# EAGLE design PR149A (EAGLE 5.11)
PID: 626
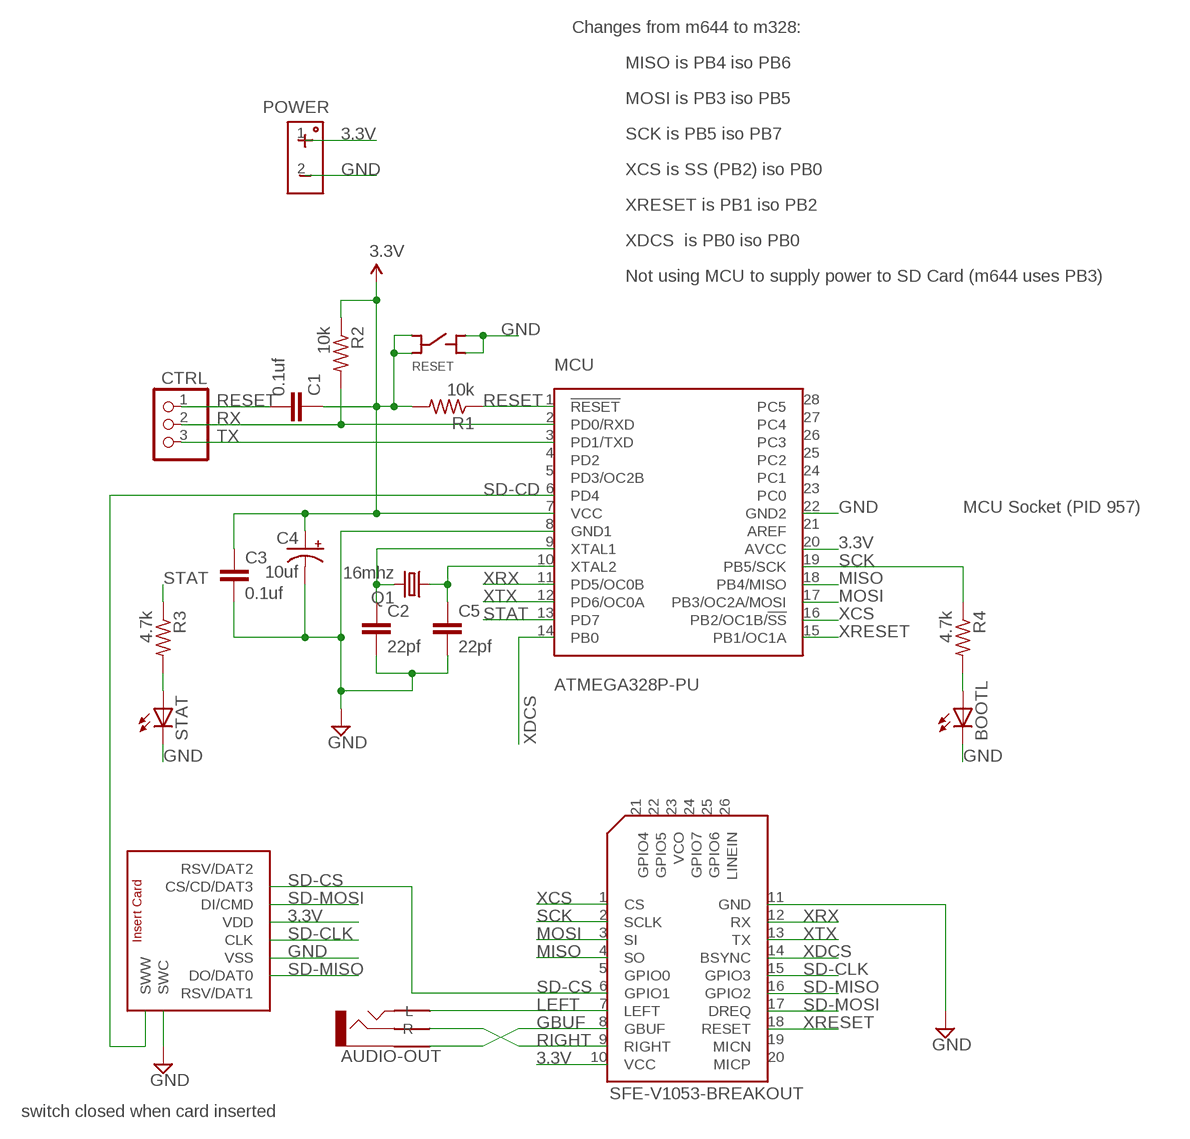
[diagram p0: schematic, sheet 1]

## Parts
AUDIO-OUT  AUDIO-JACK-STEREO-3PIN955  [AUDIO-JACK-STEREO-3PIN-955]
BOOTL  LED5MM  [LED5MM]
C1  0.1uf  C-EUC1206  [C1206]
C2  22pf  C-EUC0805  [C0805]
C3  0.1uf  C-EUC1206  [C1206]
C4  10uf  CPOL-USB  [PANASONIC_B]
C5  22pf  C-EUC0805  [C0805]
CTRL  PINHD-1X3  [1X03]
MCU  ATMEGA328P-PU  [DIL28-3]
POWER  HEADER-POWER  [HEADER-POWER]
Q1  16mhz  CRYSTALHC49S  [HC49/S]
R1  10k  R-US_M0805  [M0805]
R2  10k  R-US_R0805  [R0805]
R3  4.7k  R-US_R1206  [R1206]
R4  4.7k  R-US_R1206  [R1206]
RESET  SFE-PUSHBUTTON-SWITCH  [SFE-PUSHBUTTON-SWITCH]
SFE-V1053-BREAKOUT  SFE-VS1053-BREAKOUT  [SFE-VS1053-BREAKOUT]
STAT  LED5MM  [LED5MM]
U$1  SD-CARD-MICRO947  [SD-CARD-MICRO-947]

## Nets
3.3V: C1.1 C3.1 C4.+ MCU.7(VCC) MCU.20(AVCC) POWER.1 R1.2 R2.1 RESET.C@1(C) RESET.C@2(C) SFE-V1053-BREAKOUT.10(VCC) U$1.VDD
GBUF: AUDIO-OUT.1(COM) SFE-V1053-BREAKOUT.8(GBUF)
GND: BOOTL.K(C) C2.2 C3.2 C4.- C5.2 MCU.8(GND1) MCU.22(GND2) POWER.2 RESET.O@1(O) RESET.O@2(O) SFE-V1053-BREAKOUT.11(GND) STAT.K(C) U$1.SWC U$1.VSS
LEFT: AUDIO-OUT.2(L) SFE-V1053-BREAKOUT.7(LEFT)
MISO: MCU.18(PB4/MISO) SFE-V1053-BREAKOUT.4(SO)
MOSI: MCU.17(PB3/OC2A/MOSI) SFE-V1053-BREAKOUT.3(SI)
N$1: R3.2 STAT.A
N$2: BOOTL.A R4.2
N$3: C2.1 MCU.9(XTAL1) Q1.2
N$6: C5.1 MCU.10(XTAL2) Q1.1
RESET: C1.2 CTRL.1 MCU.1(!RESET) R1.1
RIGHT: AUDIO-OUT.3(R) SFE-V1053-BREAKOUT.9(RIGHT)
RX: CTRL.2 MCU.2(PD0/RXD) R2.2
SCK: MCU.19(PB5/SCK) R4.1 SFE-V1053-BREAKOUT.2(SCLK)
SD-CD: MCU.6(PD4) U$1.SWW
SD-CLK: SFE-V1053-BREAKOUT.15(GPIO3) U$1.CLK
SD-CS: SFE-V1053-BREAKOUT.6(GPIO1) U$1.CD/DAT3(CS/CD/DAT3)
SD-MISO: SFE-V1053-BREAKOUT.16(GPIO2) U$1.DAT0(DO/DAT0)
SD-MOSI: SFE-V1053-BREAKOUT.17(DREQ) U$1.CMD(DI/CMD)
STAT: MCU.13(PD7) R3.1
TX: CTRL.3 MCU.3(PD1/TXD)
XCS: MCU.16(PB2/OC1B/!SS) SFE-V1053-BREAKOUT.1(CS)
XDCS: MCU.14(PB0) SFE-V1053-BREAKOUT.14(BSYNC)
XRESET: MCU.15(PB1/OC1A) SFE-V1053-BREAKOUT.18(RESET)
XRX: MCU.11(PD5/OC0B) SFE-V1053-BREAKOUT.12(RX)
XTX: MCU.12(PD6/OC0A) SFE-V1053-BREAKOUT.13(TX)
Unconnected: MCU.4(PD2) MCU.5(PD3/OC2B) MCU.21(AREF) MCU.23(PC0) MCU.24(PC1) MCU.25(PC2) MCU.26(PC3) MCU.27(PC4) MCU.28(PC5) SFE-V1053-BREAKOUT.5(GPIO0) SFE-V1053-BREAKOUT.19(MICN) SFE-V1053-BREAKOUT.20(MICP) SFE-V1053-BREAKOUT.21(GPIO4) SFE-V1053-BREAKOUT.22(GPIO5) SFE-V1053-BREAKOUT.23(VCO) SFE-V1053-BREAKOUT.24(GPIO7) SFE-V1053-BREAKOUT.25(GPIO6) SFE-V1053-BREAKOUT.26(LINEIN) U$1.DAT1(RSV/DAT1) U$1.DAT2(RSV/DAT2)

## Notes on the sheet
- Changes from m644 to m328:
- MISO is PB4 iso PB6
- MOSI is PB3 iso PB5
- SCK is PB5 iso PB7
- XCS is SS (PB2) iso PB0
- XRESET is PB1 iso PB2
- XDCS  is PB0 iso PB0
- Not using MCU to supply power to SD Card (m644 uses PB3)
- MCU Socket (PID 957)
- switch closed when card inserted

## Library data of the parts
AUDIO-OUT = trl:AUDIO-JACK-STEREO-3PIN
BOOTL STAT = led:LED: LED
C1-C3 C5 = rcl:C-EU: CAPACITOR, European symbol
C4 = rcl:CPOL-US: POLARIZED CAPACITOR, American symbol
CTRL = pinhead:PINHD-1X3: PIN HEADER
MCU = trl:ATMEGA328P-PU
POWER = trl:HEADER-POWER
Q1 = crystal:CRYSTAL: CRYSTAL; OC_FARNELL: 1667008; OC_NEWARK: unknown
R1-R4 = resistor:R-US_: RESISTOR, American symbol
RESET = trl:SFE-PUSHBUTTON-SWITCH
SFE-V1053-BREAKOUT = trl:SFE-VS1053-BREAKOUT
U$1 = trl:SD-CARD-MICRO

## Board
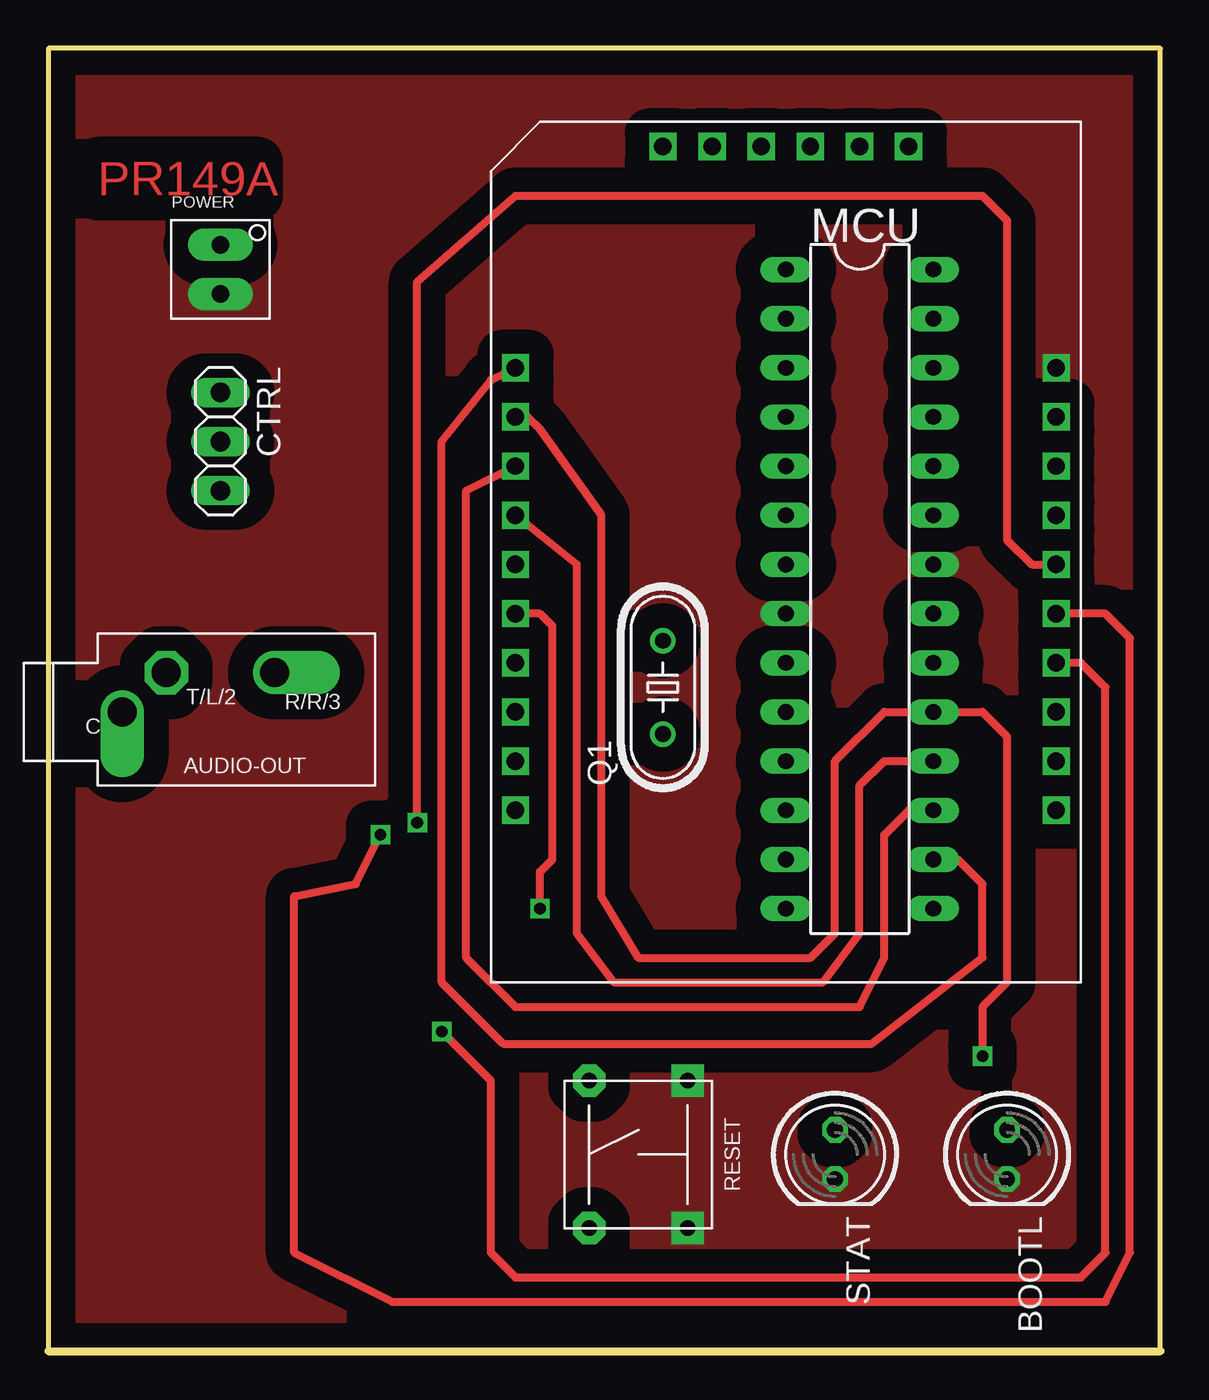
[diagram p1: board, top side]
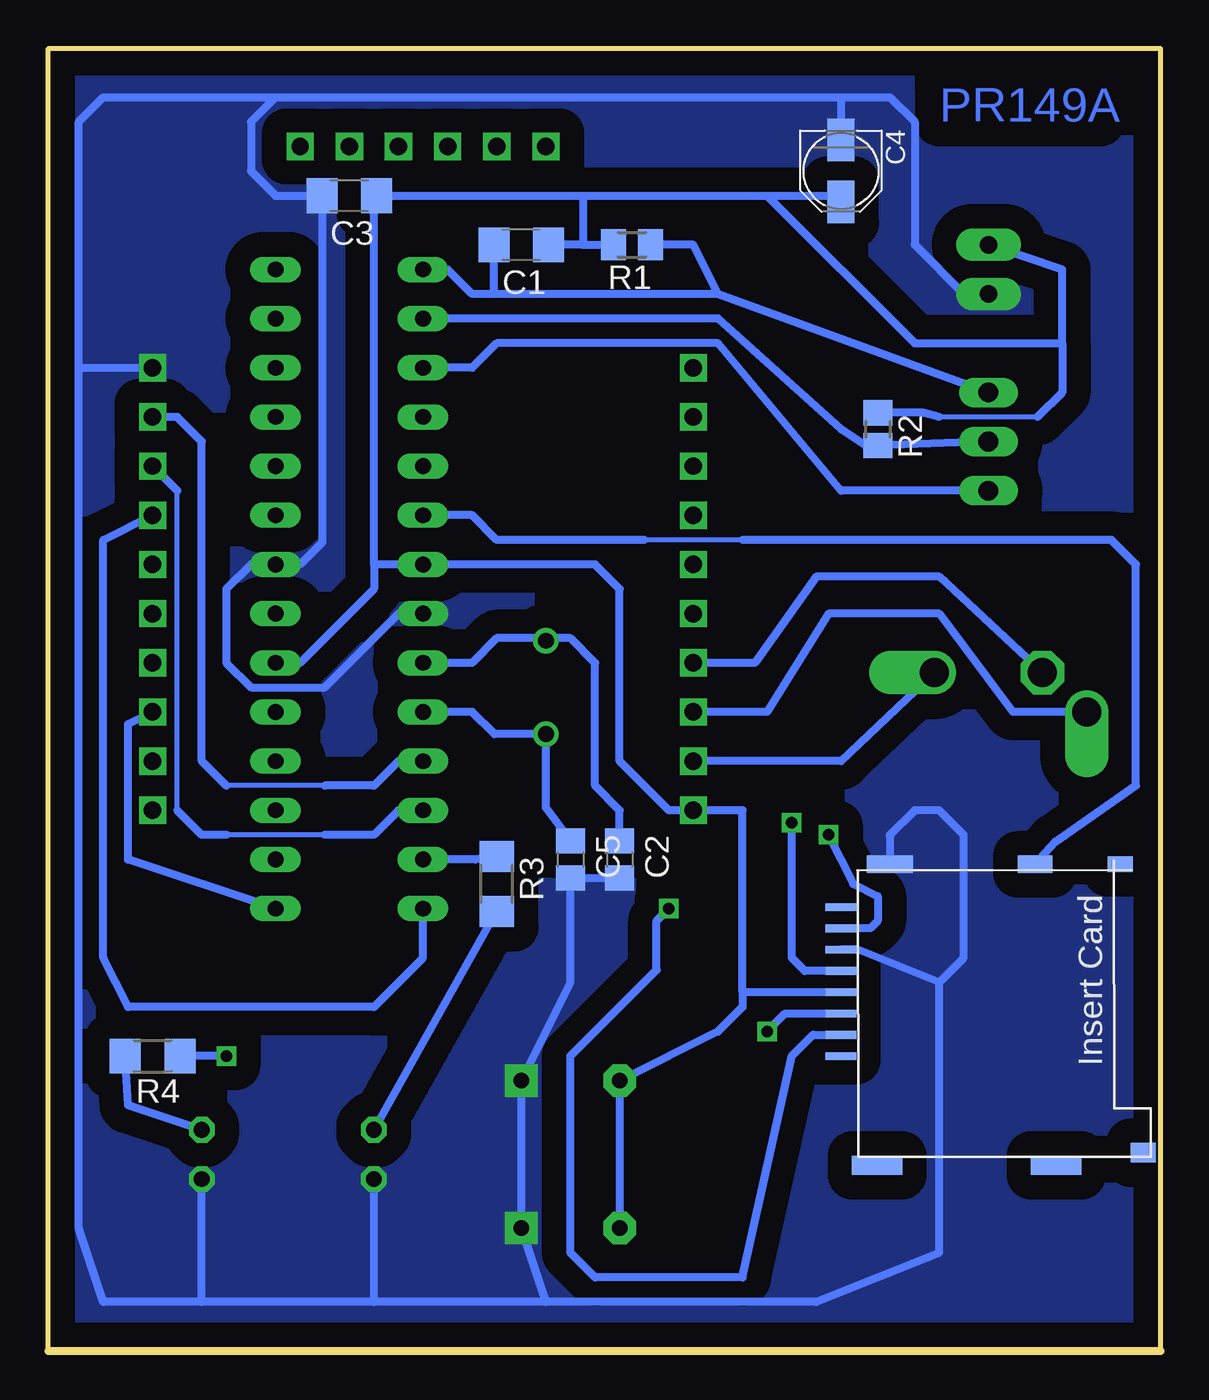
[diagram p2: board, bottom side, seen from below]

Size 57.45 x 67.3 mm. Coordinates in mm from the lower left corner, seen from the top.
Outline: 0,0 57.45,0 57.45,67.3 0,67.3 0,0
Copper layers (1*16): Top 0.035mm / dielectric 1.5mm / Bottom 0.035mm
Design rules "default": minimum track width 10mil, minimum drill 0.6mm, track to track 8mil, track to pad 8mil, pad to pad 8mil, via to via 8mil, smd to smd 8mil, copper to edge 40mil, drill to drill 8mil, minimum pad ring 10mil, minimum via ring 8mil, stop-mask expansion 4mil, vias tented up to drill 0mil, thermal gap 10mil

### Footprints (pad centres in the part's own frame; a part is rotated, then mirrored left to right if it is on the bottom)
AUDIO-JACK-STEREO-3PIN-955 = drill 1.5 offset: 1 0,0; 3 7.874,2.032 | drill 1.5 octagon: 2 2.286,2.032
LED5MM = drill 0.813 octagon: A -1.27,0; K 1.27,0
C1206 = smd 1.6 x 1.8: 1 -1.4,0; 2 1.4,0
C0805 = smd 1.3 x 1.5: 1 -0.95,0; 2 0.95,0
PANASONIC_B = smd 2.2 x 1.4: + 1.6,0; - -1.6,0
1X03 = drill 1.016 long: 1 -2.54,0; 2 0,0; 3 2.54,0
DIL28-3 = drill 0.813 long: 1 -16.51,-3.81; 2 -13.97,-3.81; 3 -11.43,-3.81; 4 -8.89,-3.81; 5 -6.35,-3.81; 6 -3.81,-3.81; 7 -1.27,-3.81; 8 1.27,-3.81; 9 3.81,-3.81; 10 6.35,-3.81; 11 8.89,-3.81; 12 11.43,-3.81; 13 13.97,-3.81; 14 16.51,-3.81; 15 16.51,3.81; 16 13.97,3.81; 17 11.43,3.81; 18 8.89,3.81; 19 6.35,3.81; 20 3.81,3.81; 21 1.27,3.81; 22 -1.27,3.81; 23 -3.81,3.81; 24 -6.35,3.81; 25 -8.89,3.81; 26 -11.43,3.81; 27 -13.97,3.81; 28 -16.51,3.81
HEADER-POWER = drill 0.9 pad 1.676 long: 1 0,1.27; 2 0,-1.27
HC49/S = drill 0.813 round: 1 -2.413,0; 2 2.413,0
M0805 = smd 1.3 x 1.6: 1 -0.95,0; 2 0.95,0
R0805 = smd 1.3 x 1.5: 1 -0.85,0; 2 0.85,0
R1206 = smd 1.6 x 1.803: 1 -1.422,0; 2 1.422,0
SFE-PUSHBUTTON-SWITCH = drill 0.8 pad 1.676 octagon: C@1 -3.81,-2.54; C@2 3.81,-2.54 | drill 0.8 pad 1.676 square: O@1 -3.81,2.54; O@2 3.81,2.54
SFE-VS1053-BREAKOUT = drill 0.9 square: 1 -13.97,10.16; 2 -13.97,7.62; 3 -13.97,5.08; 4 -13.97,2.54; 5 -13.97,0; 6 -13.97,-2.54; 7 -13.97,-5.08; 8 -13.97,-7.62; 9 -13.97,-10.16; 10 -13.97,-12.7; 11 13.97,10.16; 12 13.97,7.62; 13 13.97,5.08; 14 13.97,2.54; 15 13.97,0; 16 13.97,-2.54; 17 13.97,-5.08; 18 13.97,-7.62; 19 13.97,-10.16; 20 13.97,-12.7; 21 -6.35,21.59; 22 -3.81,21.59; 23 -1.27,21.59; 24 1.27,21.59; 25 3.81,21.59; 26 6.35,21.59
SD-CARD-MICRO-947 = smd 0.4 x 1.6: CD/DAT3 -2.71,7.62; CLK 0.59,7.62; CMD -1.61,7.62; DAT0 2.79,7.62; DAT1 3.89,7.62; DAT2 -3.81,7.62; VDD -0.51,7.62; VSS 1.69,7.62 | smd 1 x 2.6: SH1 -9.45,5.75; SH2 -9.45,-3.5 | smd 1 x 1.3: SH3 -8.8,-8 | smd 0.8 x 1.3: SH4 6.1,-6.81 | smd 0.9 x 2.4: SWC 6.1,5.09 | smd 0.9 x 1.8: SWW 6.1,-2.41

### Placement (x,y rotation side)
AUDIO-OUT  3.81,33.02 0 top
BOOTL  49.53,10.16 270 top
C1  33.02,57.15 180 bottom
C2  27.94,25.4 270 bottom
C3  41.91,59.69 180 bottom
C4  16.51,60.96 270 bottom
C5  30.48,25.4 270 bottom
CTRL  8.89,46.99 270 top
MCU  41.91,39.37 270 top
POWER  8.89,55.88 0 top
Q1  31.75,34.29 90 top
R1  27.3,57.15 180 bottom
R2  14.61,47.62 270 bottom
R3  34.29,24.13 270 bottom
R4  52.07,15.24 180 bottom
RESET  30.48,10.16 270 top
SFE-V1053-BREAKOUT  38.1,40.64 0 top
STAT  40.64,10.16 270 top
U$1  8.89,19.05 90 bottom

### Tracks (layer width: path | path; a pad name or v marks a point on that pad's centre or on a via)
3.3V
  Bottom 0.254: 6.35,48.26 11.43,48.26
  Bottom 0.406: MCU.20 44.45,35.56 40.64,39.37 40.64,40.64 | 21.59,18.54 21.59,17.78 22.86,16.51 RESET.C@1 RESET.C@2 | 5.08,52.07 5.08,49.53 6.35,48.26 | 5.08,52.07 5.08,55.88 POWER.1 | 27.94,57.15 R1.2 29.84,57.15 | U$1.VDD 21.59,18.54 | 21.59,18.54 21.59,27.94 SFE-V1053-BREAKOUT.10 25.4,27.94 27.94,30.48 27.94,39.37 29.21,40.64 MCU.7 40.64,40.64 | 29.84,59.69 C3.1 40.64,59.56 40.64,40.64 | 29.84,57.15 C1.1 | 29.84,59.69 29.84,57.15 | R2.1 12.28,48.48 11.43,48.26 | 5.08,52.07 12.7,52.07 20.32,59.69 | 29.84,59.69 20.32,59.69 | 20.32,59.69 16.84,59.69 C4.+
GBUF
  Bottom 0.406: SFE-V1053-BREAKOUT.8 20.32,33.02 17.14,38.1 11.43,38.1 7.62,33.02 AUDIO-OUT.1
GND
  Bottom 0.406: C3.2 43.18,59.82 | C3.2 43.31,41.78 44.45,40.64 MCU.22 46.99,40.64 48.26,39.37 48.26,35.56 46.99,34.29 43.18,34.29 39.37,38.1 MCU.8 | 11.43,19.05 11.43,5.08 17.78,2.54 31.75,2.54 | C2.2 C5.2 30.48,19.05 RESET.O@1 RESET.O@2 31.75,2.54 | 31.75,2.54 40.64,2.54 | 40.64,2.54 49.53,2.54 | 49.53,2.54 54.61,2.54 55.88,6.35 55.88,50.8 | 49.53,2.54 BOOTL.K | U$1.VSS 15.66,20.74 11.43,19.05 | 40.64,2.54 STAT.K | C3.2 45.72,59.69 46.99,60.96 46.99,63.5 45.72,64.77 | 55.88,50.8 55.88,63.5 54.61,64.77 45.72,64.77 | 55.88,50.8 SFE-V1053-BREAKOUT.11 | POWER.2 10.16,54.61 12.7,57.15 12.7,63.5 13.97,64.77 16.51,64.77 | 45.72,64.77 16.51,64.77 | 16.51,64.77 C4.- | U$1.SWC 13.98,26.66 12.7,27.94 11.43,27.94 10.16,26.67 10.16,20.32 11.43,19.05
  pour Bottom (isolate 1.27, no thermals): 0,67.31 57.15,67.31 57.15,0 0,0
  pour Top (isolate 1.27, no thermals): 0,67.31 57.15,67.31 57.15,0 0,0
LEFT
  Bottom 0.406: SFE-V1053-BREAKOUT.7 20.95,35.56 17.78,40.01 11.43,40.01 AUDIO-OUT.2
MISO
  Top 0.406: MCU.18 43.18,30.48 41.91,29.21 41.91,21.59 40.01,19.05 29.21,19.05 27.3,21.59 27.3,40.64 SFE-V1053-BREAKOUT.4
MOSI
  Top 0.406: MCU.17 44.45,27.94 43.18,26.67 43.18,20.32 41.91,17.78 24.13,17.78 21.59,20.32 21.59,44.45 SFE-V1053-BREAKOUT.3
N$1
  Bottom 0.406: STAT.A R3.2
N$2
  Bottom 0.406: BOOTL.A 53.34,12.7 R4.2
N$3
  Bottom 0.406: MCU.9 35.56,35.56 34.29,36.83 31.75,36.83 Q1.2 31.62,36.83 30.48,36.83 29.21,35.56 29.21,29.21 27.94,27.94 C2.1
N$6
  Bottom 0.406: 30.48,26.67 C5.1 31.75,28.07 Q1.1 34.42,31.88 35.56,33.02 MCU.10
RESET
  Bottom 0.406: CTRL.1 22.86,54.61 | 22.86,54.61 24.13,57.15 R1.1 | MCU.1 36.83,55.88 35.56,54.61 34.29,54.61 | 22.86,54.61 34.29,54.61 | C1.2 34.42,54.74 34.29,54.61
RIGHT
  Bottom 0.406: SFE-V1053-BREAKOUT.9 16.51,30.48 AUDIO-OUT.3
RX
  Bottom 0.406: CTRL.2 9.11,46.99 R2.2 15.24,46.77 16.51,47.62 22.86,53.34 MCU.2
SCK  (via drill 0.6)
  Top 0.406: SFE-V1053-BREAKOUT.2 24.77,48.26 25.4,47.62 28.57,43.18 28.57,23.5 30.48,20.32 39.37,20.32 40.64,21.59 40.64,30.48 43.18,33.02 MCU.19 48.26,33.02 49.53,31.75 49.53,19.05 48.26,17.78 v48.26,15.24
  Bottom 0.406: v48.26,15.24 R4.1
SD-CD
  Bottom 0.254: 21.59,41.91 26.67,41.91
  Bottom 0.406: U$1.SWW 5.44,26.31 1.27,29.21 1.27,40.64 2.54,41.91 21.59,41.91 | 26.67,41.91 34.29,41.91 35.56,43.18 MCU.6
SD-CLK  (via drill 0.6)
  Top 0.406: v19.05,27.3 19.05,55.24 24.13,59.69 48.26,59.69 49.53,58.42 49.53,41.91 50.8,40.64 SFE-V1053-BREAKOUT.15
  Bottom 0.406: U$1.CLK 18.37,19.64 19.05,20.32 v19.05,27.3
SD-CS  (via drill 0.6)
  Top 0.406: v25.4,22.86 25.4,24.77 26.04,25.4 26.04,37.47 25.4,38.1 SFE-V1053-BREAKOUT.6
  Bottom 0.406: U$1.CD/DAT3 17.95,16.34 19.05,15.24 21.59,3.81 29.21,3.81 30.48,5.08 30.48,15.24 26.04,19.68 26.04,22.23 v25.4,22.86
SD-MISO  (via drill 0.6)
  Top 0.406: SFE-V1053-BREAKOUT.16 54.61,38.1 55.88,36.83 55.88,5.08 54.61,2.54 17.78,2.54 12.7,5.08 12.7,23.5 15.88,24.13 v17.14,26.67
  Bottom 0.406: U$1.DAT0 14.99,21.84 14.61,22.23 14.61,23.5 15.88,24.13 v17.14,26.67
SD-MOSI  (via drill 0.6)
  Top 0.406: SFE-V1053-BREAKOUT.17 53.34,35.56 54.61,34.29 54.61,5.08 53.34,3.81 24.13,3.81 22.86,5.08 22.86,13.97 v20.32,16.51
  Bottom 0.406: U$1.CMD 19.39,17.44 v20.32,16.51
STAT
  Bottom 0.406: MCU.13 35.41,25.4 R3.1
TX
  Bottom 0.406: MCU.3 35.56,50.8 34.29,52.07 22.86,52.07 16.51,44.45 CTRL.3
XCS
  Top 0.406: SFE-V1053-BREAKOUT.1 22.86,50.16 20.32,46.99 20.32,19.05 23.5,15.88 42.55,15.88 48.26,20.32 48.26,24.13 46.99,25.4 MCU.16
XDCS
  Bottom 0.406: MCU.14 38.1,20.32 40.64,17.78 53.34,17.78 54.61,20.32 54.61,41.91 SFE-V1053-BREAKOUT.14
XRESET
  Bottom 0.406: MCU.15 53.34,25.4 53.34,32.38 SFE-V1053-BREAKOUT.18
XRX
  Bottom 0.254: 43.18,29.21 48.26,29.21
  Bottom 0.406: MCU.11 39.37,30.48 40.64,29.21 43.18,29.21 | 48.26,29.21 49.53,30.48 49.53,46.99 50.8,48.26 SFE-V1053-BREAKOUT.12
XTX
  Bottom 0.254: 43.18,26.67 48.26,26.67 | 50.8,27.94 50.8,44.45
  Bottom 0.406: MCU.12 39.37,27.94 40.64,26.67 43.18,26.67 | 48.26,26.67 49.53,26.67 50.8,27.94 | 50.8,44.45 SFE-V1053-BREAKOUT.13

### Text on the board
Top: PR149A
Bottom: PR149A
